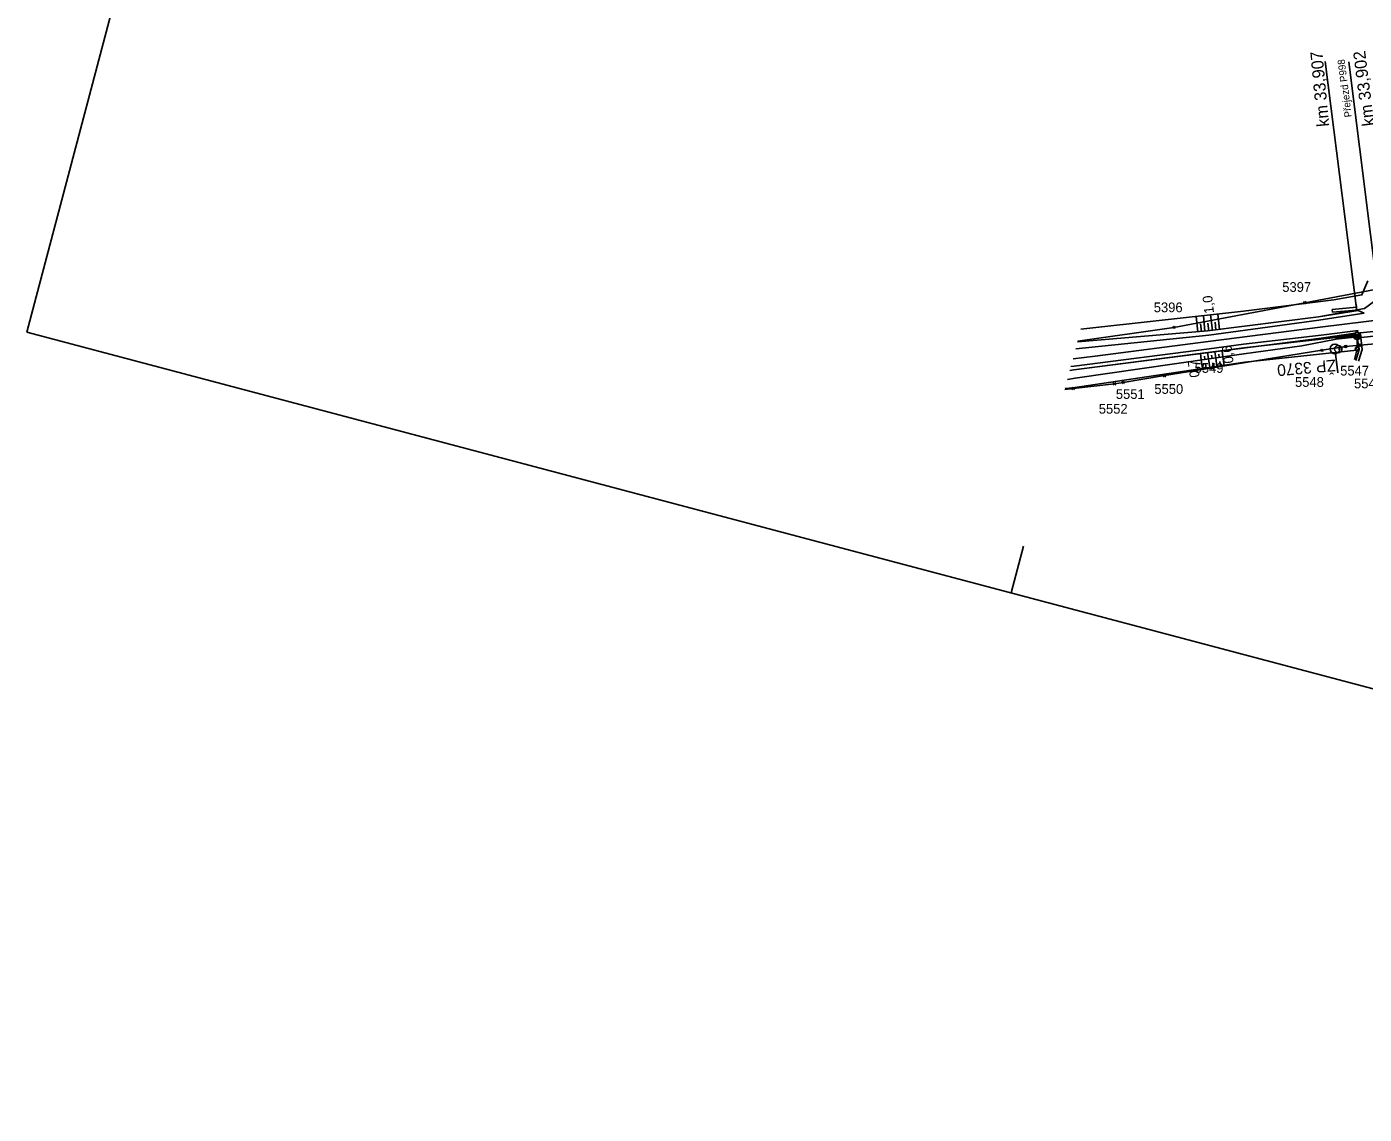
# Model space of a CAD drawing. Extents: x -805011 to -803920, y -1150790 to -1150234.
# Drawn here: x -805011.3 to -804735.5, y -1150682.7 to -1150458.6 of the extents above; entities that cross this region are included whole.
import ezdxf

# ---------------------------------------------------------------- set-up
doc = ezdxf.new("R2010")
doc.units = 0
for name, color, linetype in [('0381KM032-037P - Vrstva 1', 7, 'Continuous'), ('0381KM032-037P - Vrstva 13', 7, 'Continuous'), ('0381KM032-037P - Vrstva 17', 7, 'Continuous'), ('0381KM032-037P - Vrstva 25', 7, 'Continuous'), ('0381KM032-037P - Vrstva 36', 7, 'Continuous'), ('0381KM032-037P - Vrstva 4', 7, 'Continuous'), ('0381KM032-037P - Vrstva 43', 7, 'Continuous'), ('0381KM032-037P - Vrstva 48', 7, 'Continuous'), ('0381KM032-037P - Vrstva 49', 7, 'Continuous'), ('0381KM032-037P - Vrstva 51', 7, 'Continuous'), ('0381KM032-037P - Vrstva 9', 7, 'Continuous'), ('formát', 7, 'Continuous'), ('szdc - hran DP', 7, 'Continuous'), ('szdc - szdc_cislo', 7, 'Continuous'), ('szdc - szdc_krizek', 7, 'Continuous'), ('vyt_sit - stávající', 7, 'Continuous')]:
    doc.layers.add(name, color=color, linetype=linetype)

msp = doc.modelspace()

# ---------------------------------------------------------------- linework, layer by layer
at = {"layer": '0381KM032-037P - Vrstva 1'}
for points in [[(-804485.9, -1150487.74), (-804508.11, -1150490.55), (-804529.67, -1150493.3), (-804537.63, -1150494.31), (-804546.61, -1150495.46), (-804554.2, -1150496.42), (-804564.05, -1150497.67), (-804586.01, -1150500.48), (-804607.92, -1150503.26), (-804630.35, -1150506.11), (-804652.65, -1150508.9), (-804675.7, -1150511.78), (-804698.85, -1150514.71), (-804701.61, -1150515.06), (-804722.18, -1150517.67), (-804729.05, -1150518.54), (-804735.1, -1150519.31), (-804744.56, -1150520.5), (-804767.65, -1150523.46), (-804791, -1150526.42)], [(-804791, -1150526.42), (-804795.53, -1150527)]]:
    msp.add_lwpolyline(points, dxfattribs=at)
at = {"layer": '0381KM032-037P - Vrstva 13'}
msp.add_line((-804736.93, -1150522.56), (-804736.22, -1150522.62), dxfattribs=at)
for points in [[(-804736.32, -1150521.88), (-804741.33, -1150522.48), (-804741.32, -1150522.62), (-804736.39, -1150522.04)], [(-804736.33, -1150522.27), (-804741.29, -1150522.87), (-804741.32, -1150522.62)], [(-804741.29, -1150522.87), (-804741.28, -1150522.98), (-804736.24, -1150522.43)], [(-804736.93, -1150522.56), (-804736.54, -1150525.1), (-804737.22, -1150527.34)], [(-804736.22, -1150522.62), (-804735.92, -1150525.05), (-804736.64, -1150527.49)], [(-804736.32, -1150521.88), (-804736.39, -1150522.04), (-804736.33, -1150522.27), (-804736.24, -1150522.43)]]:
    msp.add_lwpolyline(points, dxfattribs=at)
at = {"layer": '0381KM032-037P - Vrstva 17'}
for points in [[(-804734.71, -1150510.96), (-804735.96, -1150513.84), (-804741.77, -1150514.83), (-804760.36, -1150517.2), (-804793.92, -1150520.9)], [(-804797.16, -1150533.15), (-804795.6, -1150532.98), (-804760.14, -1150527.72), (-804737.02, -1150525.24), (-804737.52, -1150527.15)]]:
    msp.add_lwpolyline(points, dxfattribs=at)
at = {"layer": '0381KM032-037P - Vrstva 25'}
for p, q in [((-804737.43, -1150521.73), (-804736.43, -1150522.84)), ((-804737.41, -1150522.86), (-804736.43, -1150521.74)), ((-804736.93, -1150523.04), (-804736.93, -1150524.54)), ((-804737.32, -1150525.02), (-804736.85, -1150524.55)), ((-804737.06, -1150525.32), (-804736.56, -1150524.82))]:
    msp.add_line(p, q, dxfattribs=at)
for centre, radius in [((-804736.94, -1150522.29), 0.749), ((-804736.93, -1150524.94), 0.4), ((-804736.93, -1150524.94), 0.4)]:
    msp.add_circle(centre, radius, dxfattribs=at)
at = {"layer": '0381KM032-037P - Vrstva 36'}
for p, q in [((-804741.54, -1150524.95), (-804741.54, -1150524.95)), ((-804741.41, -1150525.95), (-804740.91, -1150529.91))]:
    msp.add_line(p, q, dxfattribs=at)
msp.add_circle((-804741.54, -1150524.95), 1, dxfattribs=at)
at = {"layer": '0381KM032-037P - Vrstva 4'}
msp.add_line((-804738.68, -1150465.82), (-804731.99, -1150518.9), dxfattribs=at)
for points in [[(-804735.49, -1150517.59), (-804736.73, -1150517.05), (-804744.9, -1150518.34), (-804767.83, -1150521.26)], [(-804735.49, -1150517.59), (-804744.82, -1150519), (-804767.55, -1150522.1)], [(-804767.55, -1150522.1), (-804794.99, -1150524.93)], [(-804767.83, -1150521.26), (-804794.61, -1150523.51)], [(-804736.74, -1150521.15), (-804737.38, -1150521.73), (-804744.34, -1150522.73), (-804767.48, -1150525.67)], [(-804736.74, -1150521.15), (-804744.39, -1150522.13), (-804760.4, -1150524), (-804767.46, -1150524.91)], [(-804767.48, -1150525.67), (-804795.35, -1150529.3), (-804796.17, -1150529.4)], [(-804767.46, -1150524.91), (-804795.31, -1150528.51), (-804795.96, -1150528.6)]]:
    msp.add_lwpolyline(points, dxfattribs=at)
at = {"layer": '0381KM032-037P - Vrstva 43'}
msp.add_lwpolyline([(-804736.33, -1150521.65), (-804729.5, -1150520.98), (-804729.45, -1150521.92), (-804736.22, -1150522.62)], close=True, dxfattribs=at)
at = {"layer": '0381KM032-037P - Vrstva 48'}
for p, q in [((-804769.83, -1150521.43), (-804770.13, -1150518.28)), ((-804769.08, -1150521.37), (-804769.23, -1150519.78)), ((-804768.33, -1150521.3), (-804768.64, -1150518.12)), ((-804767.55, -1150521.23), (-804767.74, -1150519.63)), ((-804766.81, -1150521.13), (-804767.19, -1150517.96)), ((-804766.07, -1150521.04), (-804766.25, -1150519.46)), ((-804765.32, -1150520.94), (-804765.7, -1150517.79)), ((-804769.09, -1150527.24), (-804769.27, -1150525.92)), ((-804767.6, -1150527.03), (-804767.78, -1150525.73)), ((-804766.12, -1150526.81), (-804766.3, -1150525.53)), ((-804764.64, -1150526.59), (-804764.81, -1150525.34)), ((-804768.83, -1150529.01), (-804769.09, -1150527.24)), ((-804768.35, -1150527.13), (-804768.44, -1150526.48)), ((-804768.09, -1150528.9), (-804768.22, -1150528.02)), ((-804767.35, -1150528.79), (-804767.61, -1150527.03)), ((-804766.86, -1150526.92), (-804766.95, -1150526.27)), ((-804766.61, -1150528.68), (-804766.74, -1150527.8)), ((-804765.87, -1150528.57), (-804766.12, -1150526.81)), ((-804765.38, -1150526.7), (-804765.46, -1150526.07)), ((-804765.12, -1150528.46), (-804765.25, -1150527.58)), ((-804764.38, -1150528.35), (-804764.64, -1150526.59))]:
    msp.add_line(p, q, dxfattribs=at)
at = {"layer": '0381KM032-037P - Vrstva 49'}
for points in [[(-804731.33, -1150510.42), (-804733.06, -1150514.89), (-804735.43, -1150516.61), (-804744.9, -1150518.34), (-804767.83, -1150521.26), (-804794.61, -1150523.51)], [(-804735.96, -1150513.84), (-804741.77, -1150514.83), (-804760.36, -1150517.2), (-804793.92, -1150520.9)], [(-804796.66, -1150531.24), (-804795.08, -1150531.02), (-804760.31, -1150525.97), (-804748.35, -1150524.3), (-804741.28, -1150522.98)], [(-804741.32, -1150522.62), (-804760.31, -1150524.76), (-804795.35, -1150529.3), (-804796.17, -1150529.4)], [(-804741.32, -1150522.62), (-804741.29, -1150522.87), (-804741.28, -1150522.98)], [(-804737.02, -1150525.24), (-804760.14, -1150527.72), (-804795.6, -1150532.98), (-804797.16, -1150533.15)]]:
    msp.add_lwpolyline(points, dxfattribs=at)
at = {"layer": '0381KM032-037P - Vrstva 51'}
msp.add_lwpolyline([(-804736.22, -1150522.62), (-804735.92, -1150525.05), (-804736.64, -1150527.49)], dxfattribs=at)
at = {"layer": '0381KM032-037P - Vrstva 9'}
for p, q in [((-804737.08, -1150516.65), (-804743.56, -1150465.71)), ((-804737.11, -1150516.35), (-804742.09, -1150516.81)), ((-804742.09, -1150516.81), (-804742.04, -1150517.41)), ((-804742.04, -1150517.41), (-804737.06, -1150516.95)), ((-804737.11, -1150516.35), (-804737.17, -1150515.76)), ((-804737.06, -1150516.95), (-804737.11, -1150516.35))]:
    msp.add_line(p, q, dxfattribs=at)
at = {"layer": 'formát'}
for p, q in [((-804935.34, -1150234.42), (-805011.32, -1150521.54)), ((-804402.28, -1150682.7), (-805011.32, -1150521.54)), ((-804805.75, -1150565.59), (-804808.3, -1150575.26))]:
    msp.add_line(p, q, dxfattribs=at)
at = {"layer": 'szdc - hran DP'}
for p, q in [((-804747.72, -1150515.43), (-804723.03, -1150510.78)), ((-804774.72, -1150520.52), (-804747.72, -1150515.43)), ((-804794.57, -1150523.35), (-804774.72, -1150520.52)), ((-804744.2, -1150525.25), (-804766.8, -1150528.89)), ((-804739.31, -1150524.46), (-804744.2, -1150525.25)), ((-804736.36, -1150524.18), (-804739.31, -1150524.46)), ((-804729.97, -1150523.63), (-804736.36, -1150524.18)), ((-804776.65, -1150530.47), (-804785.22, -1150531.85)), ((-804766.8, -1150528.89), (-804776.65, -1150530.47)), ((-804795.52, -1150533.13), (-804797.21, -1150533.33)), ((-804786.96, -1150532.13), (-804795.52, -1150533.13)), ((-804785.22, -1150531.85), (-804786.96, -1150532.13))]:
    msp.add_line(p, q, dxfattribs=at)
at = {"layer": 'szdc - szdc_krizek'}
for p, q in [((-804747.46, -1150515.7), (-804747.99, -1150515.17)), ((-804747.99, -1150515.7), (-804747.46, -1150515.17)), ((-804774.46, -1150520.78), (-804774.99, -1150520.26)), ((-804774.99, -1150520.78), (-804774.46, -1150520.26)), ((-804743.94, -1150525.52), (-804744.47, -1150524.99)), ((-804744.47, -1150525.52), (-804743.94, -1150524.99)), ((-804739.05, -1150524.73), (-804739.58, -1150524.2)), ((-804739.58, -1150524.73), (-804739.05, -1150524.2)), ((-804736.09, -1150524.45), (-804736.63, -1150523.92)), ((-804736.63, -1150524.45), (-804736.09, -1150523.92)), ((-804766.54, -1150529.16), (-804767.07, -1150528.62)), ((-804767.07, -1150529.16), (-804766.54, -1150528.62)), ((-804776.39, -1150530.74), (-804776.92, -1150530.21)), ((-804776.92, -1150530.74), (-804776.39, -1150530.21)), ((-804795.26, -1150533.4), (-804795.79, -1150532.86)), ((-804795.79, -1150533.4), (-804795.26, -1150532.86)), ((-804786.7, -1150532.4), (-804787.23, -1150531.86)), ((-804787.23, -1150532.4), (-804786.7, -1150531.86)), ((-804784.96, -1150532.11), (-804785.49, -1150531.58)), ((-804785.49, -1150532.11), (-804784.96, -1150531.58))]:
    msp.add_line(p, q, dxfattribs=at)
at = {"layer": 'vyt_sit - stávající'}
msp.add_line((-804740.89, -1150524.99), (-804740.79, -1150524.99), dxfattribs=at)
msp.add_circle((-804740.83, -1150524.99), 0.756, dxfattribs=at)

# ---------------------------------------------------------------- texts
at = {"layer": '0381KM032-037P - Vrstva 4'}
for s, height, p in [('km 33,902', 2.5, (-804733.36, -1150478.88)), ('Přejezd P998', 1.5, (-804738.02, -1150477.13))]:
    msp.add_text(s, height=height, rotation=97.1938, dxfattribs=at).set_placement(p)
at = {"layer": '0381KM032-037P - Vrstva 48'}
for s, rotation, p in [('1,0', 96.2855, (-804766.46, -1150517.56)), ('0,6', 97.4164, (-804762.42, -1150527.82)), ('0,7', 98.2601, (-804769.42, -1150530.71))]:
    msp.add_text(s, height=2, rotation=rotation, dxfattribs=at).set_placement(p)
at = {"layer": '0381KM032-037P - Vrstva 9'}
msp.add_text('km 33,907', height=2.5, rotation=95.2837, dxfattribs=at).set_placement((-804742.69, -1150479.05))
at = {"layer": 'szdc - szdc_cislo'}
for s, p in [('5397', (-804752.39, -1150513.2)), ('5396', (-804778.89, -1150517.39)), ('5549', (-804770.47, -1150529.89)), ('5547', (-804740.45, -1150530.44)), ('5548', (-804749.76, -1150532.78)), ('5546', (-804737.59, -1150533.08)), ('5551', (-804786.71, -1150535.26)), ('5550', (-804778.77, -1150534.22)), ('5552', (-804790.23, -1150538.31))]:
    msp.add_text(s, height=2, dxfattribs=at).set_placement(p)
at = {"layer": 'vyt_sit - stávající'}
msp.add_text('ŽP 3370', height=2.4, rotation=185, dxfattribs=at).set_placement((-804741.45, -1150527.14))

doc.saveas('drawing.dxf')
